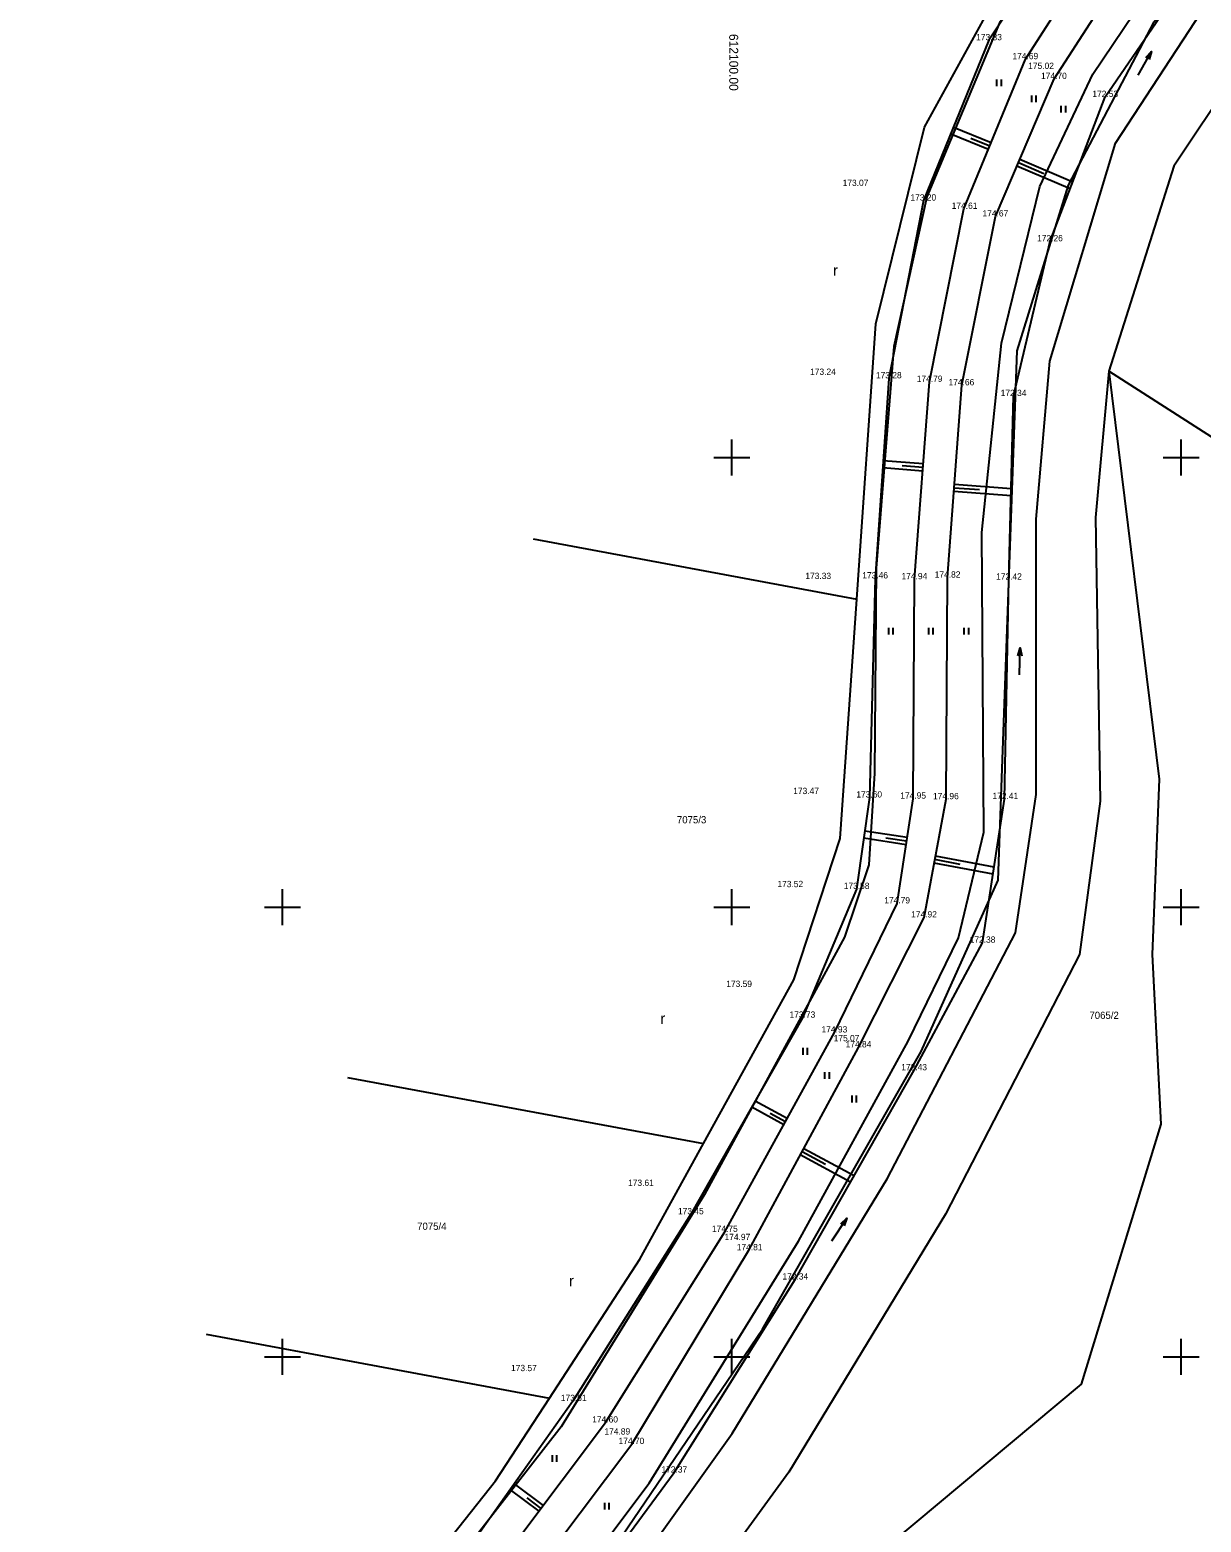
# Model space of a CAD drawing. Extents: x -612546 to -611926, y -1201932 to -1200444.
# Drawn here: x -612178.1 to -612047.8, y -1201768.4 to -1201602.4 of the extents above; entities that cross this region are included whole.
import ezdxf

# ---------------------------------------------------------------- set-up
doc = ezdxf.new("R2010")
doc.units = 0
for name, color, linetype in [('14 hrana pata svahu', 7, 'Continuous'), ('15 šrafy', 7, 'Continuous'), ('61 legenda křížky', 7, 'Continuous'), ('Hranice parcel', 7, 'Continuous'), ('Parcelní čísla', 7, 'Continuous'), ('Vnitřní kresba', 7, 'Continuous'), ('Vrstva 36', 7, 'Continuous'), ('Vrstva 45', 7, 'Continuous'), ('výška bodu', 7, 'Continuous')]:
    doc.layers.add(name, color=color, linetype=linetype)

msp = doc.modelspace()

# ---------------------------------------------------------------- linework, layer by layer
at = {"layer": '14 hrana pata svahu'}
for points in [[(-612057.63, -1201582.88), (-612071.39, -1201603.6), (-612078.67, -1201621.43), (-612082.54, -1201641.2), (-612084.04, -1201663.45), (-612084.67, -1201687.81), (-612086.12, -1201697.99), (-612092.15, -1201712.3), (-612104.56, -1201734.15), (-612117.68, -1201754.92), (-612131.54, -1201774.52), (-612146.69, -1201793.8), (-612160.09, -1201810.84), (-612170.67, -1201824.21), (-612178.79, -1201837.39), (-612188.62, -1201833.24)], [(-612188.62, -1201833.24), (-612178.38, -1201842.08), (-612166.95, -1201827.44), (-612156.25, -1201813.45), (-612143.51, -1201796.15), (-612128.5, -1201776.54), (-612114.05, -1201757.31), (-612100.78, -1201736.11), (-612088.59, -1201713.94), (-612081.61, -1201699.59), (-612079.83, -1201687.94), (-612079.69, -1201663.54), (-612078, -1201641.59), (-612074.18, -1201622.35), (-612067.33, -1201605.71), (-612054.19, -1201585.24)], [(-612175.88, -1201845.11), (-612164.34, -1201830.03), (-612153.47, -1201815.42), (-612140.49, -1201798.24), (-612125.56, -1201778.9), (-612111.14, -1201759.71), (-612098.11, -1201738.16), (-612085.91, -1201715.6), (-612078.62, -1201701.15), (-612076.17, -1201688), (-612076, -1201663.36), (-612074.42, -1201641.97), (-612070.66, -1201623.2), (-612064.14, -1201607.91), (-612050.9, -1201587.38)], [(-612170.22, -1201849.2), (-612158.9, -1201833.69), (-612148.62, -1201818.79), (-612135.22, -1201801.91), (-612120.79, -1201782.4), (-612106.4, -1201762.88), (-612092.94, -1201741.41), (-612079.72, -1201718.14), (-612072.11, -1201703.96), (-612069.66, -1201687.98), (-612069.17, -1201663.58), (-612068.66, -1201643.17), (-612064.59, -1201625.96), (-612058.46, -1201609.91), (-612045.84, -1201591.45)]]:
    msp.add_lwpolyline(points, dxfattribs=at)
at = {"layer": '15 šrafy'}
for p, q in [((-612075.34, -1201613.26), (-612071.15, -1201614.99)), ((-612075.64, -1201614), (-612071.45, -1201615.73)), ((-612073.41, -1201614.49), (-612071.3, -1201615.36)), ((-612065.28, -1201618.47), (-612068.12, -1201617.25)), ((-612062.08, -1201619.39), (-612067.97, -1201616.88)), ((-612062.37, -1201620.14), (-612068.28, -1201617.62)), ((-612083.16, -1201650.34), (-612078.7, -1201650.68)), ((-612083.21, -1201651.13), (-612078.76, -1201651.48)), ((-612081.04, -1201650.9), (-612078.73, -1201651.08)), ((-612068.94, -1201654.27), (-612075.29, -1201653.8)), ((-612072.45, -1201653.61), (-612075.26, -1201653.4)), ((-612068.92, -1201653.47), (-612075.23, -1201653)), ((-612085.2, -1201691.51), (-612080.49, -1201692.23)), ((-612085.31, -1201692.31), (-612080.61, -1201693.03)), ((-612082.86, -1201692.28), (-612080.55, -1201692.63)), ((-612070.94, -1201696.33), (-612077.5, -1201695.11)), ((-612074.6, -1201695.25), (-612077.42, -1201694.72)), ((-612070.82, -1201695.54), (-612077.35, -1201694.33)), ((-612097.39, -1201721.53), (-612093.84, -1201723.48)), ((-612097.79, -1201722.22), (-612094.22, -1201724.18)), ((-612095.72, -1201722.9), (-612094.03, -1201723.83)), ((-612086.79, -1201730.58), (-612092.38, -1201727.56)), ((-612089.56, -1201728.63), (-612092.19, -1201727.21)), ((-612086.39, -1201729.89), (-612092, -1201726.86)), ((-612124.66, -1201764.79), (-612121.47, -1201767.18)), ((-612124.2, -1201764.14), (-612120.99, -1201766.54)), ((-612122.8, -1201765.69), (-612121.23, -1201766.86))]:
    msp.add_line(p, q, dxfattribs=at)
at = {"layer": '61 legenda křížky'}
for p, q in [((-612100, -1201652), (-612100, -1201648)), ((-612050, -1201652), (-612050, -1201648)), ((-612102, -1201650), (-612098, -1201650)), ((-612052, -1201650), (-612048, -1201650)), ((-612150, -1201702), (-612150, -1201698)), ((-612100, -1201702), (-612100, -1201698)), ((-612050, -1201702), (-612050, -1201698)), ((-612152, -1201700), (-612148, -1201700)), ((-612102, -1201700), (-612098, -1201700)), ((-612052, -1201700), (-612048, -1201700)), ((-612150, -1201752), (-612150, -1201748)), ((-612100, -1201752), (-612100, -1201748)), ((-612050, -1201752), (-612050, -1201748)), ((-612152, -1201750), (-612148, -1201750)), ((-612102, -1201750), (-612098, -1201750)), ((-612052, -1201750), (-612048, -1201750))]:
    msp.add_line(p, q, dxfattribs=at)
at = {"layer": 'Hranice parcel'}
msp.add_line((-612045.15, -1201648.68), (-612058.05, -1201640.39), dxfattribs=at)
for points in [[(-612177.46, -1201854.09), (-612171.97, -1201847.65), (-612125.97, -1201786.38), (-612109.19, -1201764.04), (-612092.57, -1201737.14), (-612080.39, -1201714.9), (-612074.78, -1201703.41), (-612071.98, -1201691.65), (-612072.2, -1201658.35), (-612070, -1201637.27), (-612065.73, -1201619.85), (-612059.82, -1201607.37), (-612039.46, -1201577.1), (-612017, -1201547.24), (-612004.68, -1201526.81), (-611998.92, -1201511.99), (-611996.24, -1201493.62), (-611996.58, -1201479.8), (-612000.74, -1201455.02), (-612027.1, -1201355.18), (-612050.25, -1201267.11)], [(-612060.22, -1201274.37), (-612037.81, -1201356.84), (-612011.62, -1201457.28), (-612007.48, -1201483.41), (-612008.37, -1201502.54), (-612012.46, -1201517.21), (-612025.5, -1201540.7), (-612047.75, -1201570.04), (-612070.24, -1201601.65), (-612078.31, -1201621), (-612081.97, -1201637.65), (-612083.96, -1201662.29), (-612084.12, -1201685.12), (-612084.75, -1201695.31), (-612087.47, -1201703.35), (-612103.05, -1201731.95), (-612118.98, -1201757.79), (-612136.57, -1201780.34), (-612179.16, -1201837.25), (-612189.22, -1201833.81)], [(-611996.06, -1201535.15), (-612001.15, -1201544.98), (-612031.12, -1201588.08), (-612050.83, -1201617.6), (-612058.05, -1201640.39)], [(-612086.09, -1201665.74), (-612083.97, -1201635.12), (-612078.56, -1201613.28), (-612071.21, -1201599.94)], [(-612058.05, -1201640.39), (-612059.55, -1201656.68), (-612059.01, -1201688.21), (-612061.34, -1201705.25), (-612076.22, -1201734.13), (-612093.67, -1201762.82), (-612129.56, -1201812.16), (-612153.59, -1201844.29), (-612161.99, -1201854.93), (-612167.05, -1201861.67), (-612182.62, -1201885.13)], [(-612058.05, -1201640.39), (-612052.46, -1201685.78), (-612053.25, -1201705.28), (-612052.26, -1201724.13), (-612061.14, -1201753.05), (-612082.33, -1201770.75), (-612093.73, -1201789.71), (-612101.27, -1201800.38), (-612106.23, -1201814.07), (-612115.7, -1201831.27), (-612125.23, -1201843.35), (-612136.68, -1201849.84), (-612144.46, -1201853.06), (-612145.1, -1201866.35)], [(-612122.1, -1201659.05), (-612086.09, -1201665.74)], [(-612103.15, -1201726.29), (-612093.11, -1201708.08), (-612087.94, -1201692.38), (-612086.09, -1201665.74)], [(-612142.75, -1201718.93), (-612103.15, -1201726.29)], [(-612120.3, -1201754.59), (-612110.23, -1201739.14), (-612103.15, -1201726.29)], [(-612158.49, -1201747.49), (-612120.3, -1201754.59)], [(-612189.22, -1201833.81), (-612176.37, -1201823.43), (-612164.9, -1201812.54), (-612126.3, -1201763.8), (-612120.3, -1201754.59)]]:
    msp.add_lwpolyline(points, dxfattribs=at)
at = {"layer": 'Vnitřní kresba'}
for points in [[(-612170.38, -1201848.81), (-612152.03, -1201823.55), (-612114.84, -1201773.75), (-612096.57, -1201746.92), (-612078.95, -1201716.04), (-612070.37, -1201697.01), (-612068.25, -1201638.15), (-612062.56, -1201619.7), (-612053.03, -1201601.55), (-612018.56, -1201552.89), (-611999.85, -1201519.56), (-611995.35, -1201499.82), (-611993.63, -1201480.57), (-612000.19, -1201450.02), (-612024.45, -1201357.81), (-612050.25, -1201267.11)], [(-612167.45, -1201850.95), (-612159.31, -1201839.87), (-612135.2, -1201807.83), (-612099.97, -1201758.55), (-612082.71, -1201730.21), (-612068.43, -1201702.85), (-612066.16, -1201687.46), (-612066.16, -1201656.85), (-612064.63, -1201639.3), (-612057.32, -1201615.06), (-612036.83, -1201583.77), (-612007.13, -1201540.95), (-611995.21, -1201517.05), (-611990.85, -1201487.68), (-611992.18, -1201466.53), (-612005.11, -1201415.22), (-612025.88, -1201339.7), (-612042.61, -1201277.13), (-612043.67, -1201266.17)]]:
    msp.add_lwpolyline(points, dxfattribs=at)
at = {"layer": 'Vrstva 36'}
for p, q in [((-612070.5, -1201608.71), (-612070.5, -1201607.96)), ((-612070, -1201608.71), (-612070, -1201607.96)), ((-612066.63, -1201610.48), (-612066.63, -1201609.73)), ((-612066.13, -1201610.48), (-612066.13, -1201609.73)), ((-612063.35, -1201611.65), (-612063.35, -1201610.9)), ((-612062.85, -1201611.65), (-612062.85, -1201610.9)), ((-612082.55, -1201669.7), (-612082.55, -1201668.95)), ((-612082.05, -1201669.7), (-612082.05, -1201668.95)), ((-612078.1, -1201669.7), (-612078.1, -1201668.95)), ((-612077.6, -1201669.7), (-612077.6, -1201668.95)), ((-612074.14, -1201669.7), (-612074.14, -1201668.95)), ((-612073.64, -1201669.7), (-612073.64, -1201668.95)), ((-612092.08, -1201716.41), (-612092.08, -1201715.66)), ((-612091.58, -1201716.41), (-612091.58, -1201715.66)), ((-612089.64, -1201719.1), (-612089.64, -1201718.35)), ((-612089.14, -1201719.1), (-612089.14, -1201718.35)), ((-612086.62, -1201721.71), (-612086.62, -1201720.96)), ((-612086.12, -1201721.71), (-612086.12, -1201720.96)), ((-612119.95, -1201761.68), (-612119.95, -1201760.93)), ((-612119.45, -1201761.68), (-612119.45, -1201760.93)), ((-612114.14, -1201766.98), (-612114.14, -1201766.23)), ((-612113.64, -1201766.98), (-612113.64, -1201766.23))]:
    msp.add_line(p, q, dxfattribs=at)
at = {"layer": 'Vrstva 45'}
for p, q in [((-612054.79, -1201607.49), (-612053.33, -1201604.87)), ((-612068.01, -1201674.17), (-612067.92, -1201671.18)), ((-612088.86, -1201737.1), (-612087.22, -1201734.59))]:
    msp.add_line(p, q, dxfattribs=at)
for points in [[(-612053.96, -1201605.52), (-612053.33, -1201604.87), (-612053.56, -1201605.75)], [(-612068.18, -1201672.05), (-612067.92, -1201671.18), (-612067.72, -1201672.06)], [(-612087.89, -1201735.2), (-612087.22, -1201734.59), (-612087.5, -1201735.45)]]:
    msp.add_lwpolyline(points, dxfattribs=at)

# ---------------------------------------------------------------- texts
at = {"layer": '61 legenda křížky'}
msp.add_text('612100.00', height=1, rotation=270, dxfattribs=at).set_placement((-612100.29, -1201602.9))
at = {"layer": 'Parcelní čísla'}
for s, p in [('7075/3', (-612106.11, -1201690.68)), ('7065/2', (-612060.22, -1201712.43)), ('7075/4', (-612135.01, -1201735.89))]:
    msp.add_text(s, height=0.8, dxfattribs=at).set_placement(p)
at = {"layer": 'Vrstva 36'}
for p in [(-612088.73, -1201629.79), (-612107.94, -1201712.98), (-612118.1, -1201742.16)]:
    msp.add_text('r', height=1.2, dxfattribs=at).set_placement(p)
at = {"layer": 'výška bodu'}
for s, p in [('173.33', (-612072.82, -1201603.6)), ('174.69', (-612068.78, -1201605.71)), ('175.02', (-612067.03, -1201606.79)), ('174.70', (-612065.6, -1201607.91)), ('172.53', (-612059.89, -1201609.91)), ('173.07', (-612087.67, -1201619.8)), ('173.20', (-612080.13, -1201621.43)), ('174.61', (-612075.54, -1201622.35)), ('174.67', (-612072.11, -1201623.2)), ('172.26', (-612066.04, -1201625.96)), ('173.24', (-612091.29, -1201640.81)), ('173.28', (-612083.97, -1201641.2)), ('174.79', (-612079.43, -1201641.59)), ('174.66', (-612075.89, -1201641.97)), ('172.34', (-612070.09, -1201643.17)), ('173.33', (-612091.82, -1201663.52)), ('173.46', (-612085.49, -1201663.45)), ('174.94', (-612081.12, -1201663.54)), ('174.82', (-612077.43, -1201663.36)), ('172.42', (-612070.6, -1201663.58)), ('173.47', (-612093.17, -1201687.43)), ('173.60', (-612086.15, -1201687.81)), ('174.95', (-612081.26, -1201687.94)), ('174.96', (-612077.62, -1201688)), ('172.41', (-612071, -1201687.98)), ('173.52', (-612094.93, -1201697.78)), ('173.58', (-612087.55, -1201697.99)), ('174.79', (-612083.04, -1201699.59)), ('174.92', (-612080.05, -1201701.15)), ('172.38', (-612073.54, -1201703.96)), ('173.59', (-612100.62, -1201708.88)), ('173.73', (-612093.58, -1201712.3)), ('174.93', (-612090.02, -1201713.94)), ('175.07', (-612088.67, -1201714.92)), ('174.84', (-612087.34, -1201715.6)), ('172.43', (-612081.15, -1201718.14)), ('173.61', (-612111.54, -1201731)), ('173.45', (-612105.99, -1201734.15)), ('174.75', (-612102.21, -1201736.11)), ('174.97', (-612100.81, -1201737.03)), ('174.81', (-612099.45, -1201738.16)), ('172.34', (-612094.37, -1201741.41)), ('173.57', (-612124.56, -1201751.6)), ('173.51', (-612119.02, -1201754.92)), ('174.60', (-612115.53, -1201757.31)), ('174.89', (-612114.17, -1201758.65)), ('174.70', (-612112.6, -1201759.71)), ('172.37', (-612107.83, -1201762.88))]:
    msp.add_text(s, height=0.7, dxfattribs=at).set_placement(p)

doc.saveas('drawing.dxf')
